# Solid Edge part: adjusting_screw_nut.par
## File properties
Title: Adjusting screw nut
Author: Abhinav Rai
Template: Normal.par
Last saved by: Cadcim
Revision: 13
Application: Solid Edge
Material: aluminum
Accuracy: 0.99
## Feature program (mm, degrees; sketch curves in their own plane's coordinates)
sketch for "unnamed RevolvedProtrusion 1" plane through (0, 0, 0) normal (0, -1, 0) x-axis (1, 0, 0)
  line (38.1, 9.7462) -> (74.676, 9.7462)
  line (76.2, 8.2222) -> (74.676, 9.7462)
  line (76.2, -26.8298) -> (76.2, 8.2222)
  line (76.2, -26.8298) -> (74.676, -28.3538)
  line (74.676, -28.3538) -> (47.625, -28.3538)
  line (47.625, -28.3538) -> (47.625, -60.1038)
  line (47.625, -60.1038) -> (38.1, -60.1038)
  line (38.1, -60.1038) -> (38.1, 9.7462)
revolve "unnamed RevolvedProtrusion 1" add full turn 360 deg
sketch for "Hole_1" plane through (76.2, 0, 0) normal (1, 0, 0) x-axis (0, 1, 0)
  hole centre (0, -9.3038) bore radius 9.5123
hole "Hole_1" diameter 19.0246 finite  VBottomAngle = 118 deg
pattern "unnamed Pattern 1" of "Hole_1"
pattern "unnamed Pattern 2"
sketch for "ExtrudedProtrusion_3" #1 plane through (0, 0, 9.7462) normal (0, 0, 1) x-axis (1, 0, 0)
sketch for "ExtrudedProtrusion_3" #2 plane through (0, 0, 9.7462) normal (0, 0, 1) x-axis (1, 0, 0)
  circle centre (0, 0) radius 47.625
extrude "ExtrudedProtrusion_3" add finite 31.75 along +normal
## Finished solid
Body 1: solid body, 18 faces, 18 edges, 4 vertices.
  Faces by surface: cylinder 8, cone 6, plane 4
  Edges by curve: circle 14, intersection 4
Bounding box of the edges (mm): 152.400 x 152.400 x 101.600, from (-76.2, -76.2, -60.1038) to (76.2, 76.2, 41.4962).
Cylindrical faces by radius (mm): R9.5123 x4, R38.1 x1, R47.625 x2, R76.2 x1
Conical faces (half-angle, radius in mm at the cone's reference point): 45 deg R74.676 x1, 45 deg R76.2 x1, 59 deg R9.5123 x4
Planar faces by outward normal: +z 2, -z 2
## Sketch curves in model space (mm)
circle centre (0, 0, 9.7462) radius 38.1
circle centre (0, 0, 9.7462) radius 47.625
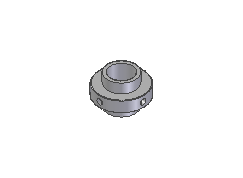
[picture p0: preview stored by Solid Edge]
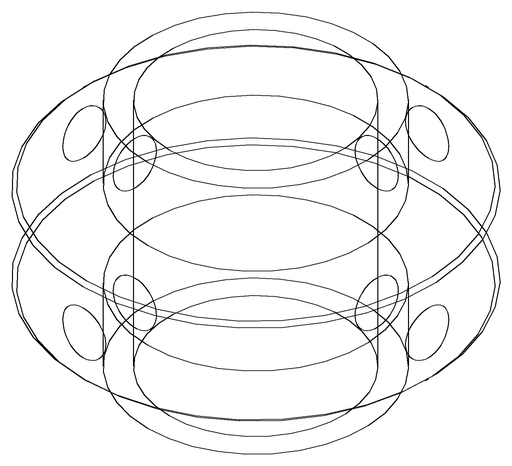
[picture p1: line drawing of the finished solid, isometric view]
